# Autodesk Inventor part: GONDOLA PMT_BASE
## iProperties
Shininess: 64.0
Length Units: 11272
Angle Units: 11279
Time Units: 11290
Mass Units: 11286
Length Display Precision: 3
Angle Display Precision: 2
Compacted: True
Part Number: GONDOLA PMT_BASE
Document SubType Name: Modeling
Created: 2004-08
Designer: John Blackburn
Manufacturer: Standard
Standards Organization: Custom
Material: Aluminum-6061-AHC
Density: 0.0
Volumn: 0.0
Area: 0.0
PropertySet Name: Model Information
Control State: 0
Master: False
Checked Out: False
Author: John Blackburn
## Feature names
1. Base1
